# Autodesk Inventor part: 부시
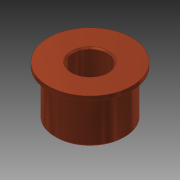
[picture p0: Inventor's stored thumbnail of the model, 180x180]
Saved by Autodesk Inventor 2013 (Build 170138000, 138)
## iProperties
Created: 2015-10
Part Number: 부시
Document SubType Name: Modeling
Designer: mdu
Density: 7.86 g/cm^3
Material: 강철, 연강
Mass: 424.247 g
Surface Area: 128.313 cm^2
Volume: 53.9754 cm^3
Author: mdu
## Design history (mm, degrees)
sketch "스케치1"
  geometry: C1 r 31 at (0, 0) reference; C2 r 25 at (0, 0) reference; C3 r 30 at (0, 0) reference; 1 further point
  node "참조1"
  node "참조2"
  node "참조4"
extrude "돌출1" new body sketch "스케치1" distance "d0" = 3; taper "d1" = 0 deg
extrude "돌출2" join sketch "스케치1" distance "d2" = 35; taper "d3" = 0 deg
chamfer "모따기1" distance "d6" = 1; stored, may be unused: second distance "d7" = 2, angle "d8" = 45 deg
sketch "스케치3"
  geometry: C1 r 12.5 at (0, 0); 1 further point
  constraints: 1 centre point, 1 coincident
  dimensions: "d13" = 25 diameter of C1
extrude "돌출4" cut sketch "스케치3" stored distance "d14" = 10; taper "d15" = 0 deg
chamfer "모따기3" distance "d16" = 1; stored, may be unused: second distance "d17" = 2, angle "d18" = 45 deg
node "솔리드1"
